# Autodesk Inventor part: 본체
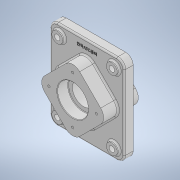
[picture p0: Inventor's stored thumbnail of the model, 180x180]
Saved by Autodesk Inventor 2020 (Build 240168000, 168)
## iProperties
Created: 2021-07
Part Number: 본체
Material: 일반
Document SubType Name: Modeling
Designer: Owner
Density: 1 g/cm^3
Appearance: 기본값
Mass: 807.977 g
Surface Area: 961.758 cm^2
Volume: 807.977 cm^3
Author: Owner
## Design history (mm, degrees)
sketch "스케치1"
  geometry: L1 (75, -90)-(-75, -90); L2 (-75, -90)-(-75, 90); L3 (-75, 90)-(75, 90); L4 (75, 90)-(75, -90); L5 (75, -90)-(-75, 90); L6 (-75, -90)-(75, 90); 1 further point
  constraints: 12 end point, 2 midpoint, 2 parallel, 1 horizontal, 1 perpendicular
  dimensions: "d0" = 150 distance of L2.end L3.end; "d1" = 180 distance of L1.end L2.end
extrude "돌출1" new body sketch "스케치1" stored distance "d2" = 18; taper "d3" = 0 deg
fillet "모깎기1" dims "d4" = 15
sketch "스케치2" dims "d7" = 29
  geometry: L1 (0, -70.711)-(-70.711, 0); L2 (-70.711, 0)-(0, 70.711); L3 (0, 70.711)-(70.711, 0); L4 (70.711, 0)-(0, -70.711); L5 (0, -70.711)-(0, 70.711); L6 (-70.711, 0)-(70.711, 0); 4 further points
  constraints: 12 end point, 4 midpoint, 2 parallel, 1 coincident, 1 horizontal alignment, 1 perpendicular, 1 vertical alignment
  dimensions: "d70" = 100 distance of L1.start L1.end
extrude "돌출2" join sketch "스케치2" distance "d7" = 29; taper "d8" = 0 deg
sketch "스케치3"
  geometry: L1 (-14.142, -56.569)-(-56.569, -14.142); L2 (-56.569, 14.142)-(-14.142, 56.569); L3 (14.142, 56.569)-(56.569, 14.142); L4 (56.569, -14.142)-(14.142, -56.569); L5 (0, -70.711)-(0, 70.711); L6 (-70.711, 0)-(70.711, 0); A1 r 20 centre (-42.426, 0) between (-56.569, 14.142) and (-56.569, -14.142); A2 r 20 centre (0, -42.426) between (-14.142, -56.569) and (14.142, -56.569); A3 r 20 centre (42.426, 0) between (56.569, -14.142) and (56.569, 14.142); A4 r 20 centre (0, 42.426) between (14.142, 56.569) and (-14.142, 56.569); 3 further points
  constraints: 12 end point, 8 point on circle, 8 point on line, 8 tangent, 4 centre point, 4 midpoint, 3 equal radius, 2 parallel, 1 horizontal alignment, 1 perpendicular, 1 vertical alignment
  dimensions: "d9" = 100 distance of L5.start L6.start; "d12" = 20 radius of A1 (derived)
extrude "돌출3" join sketch "스케치3" distance "d10" = 23; taper "d11" = 0 deg
sketch "스케치4"
  geometry: C1 r 11 at (-55, 70); C2 r 11 at (55, 70); C3 r 11 at (55, -70); C4 r 11 at (-55, -70); 1 further point
  constraints: 4 centre point, 2 horizontal alignment, 2 vertical alignment
  dimensions: "d13" = 22 diameter of C1; "d14" = 22 diameter of C2; "d15" = 22 diameter of C3; "d16" = 22 diameter of C4; "d17" = 110 distance of C1.centre C2.centre; "d18" = 55 horizontal distance of point (0, 0) C1.centre (= 0.5 x d17); "d19" = 140 distance of C3.centre C2.centre; "d20" = 70 vertical distance of point (0, 0) C2.centre (= 0.5 x d19)
extrude "돌출4" join sketch "스케치4" distance "d21" = 5; taper "d22" = 0 deg
sketch "스케치5"
  geometry: C1 r 11 at (0, 0) reference; C2 r 11 at (110, 0) reference; C3 r 11 at (110, -140) reference; C4 r 11 at (0, -140) reference; 5 further points
  constraints: 4 coincident
hole "구멍1" sketch "스케치5" at (0, 0), (110, 0), (110, -140), (0, -140) diameter "d23" = 11; stored, may be unused: countersink angle "d27" = 90 deg, drill point angle "d29" = 118 deg; dims "d24" = 6, "d25" = 4, "d26" = 2, "d28" = 8
sketch "스케치6"
  geometry: 2 further points
  constraints: 1 vertical alignment
  dimensions: "d30" = 48 distance of point (0, 0) point (0, 48)
hole "구멍2" sketch "스케치6" at (0, 48) diameter "d31" = 4.917; stored, may be unused: countersink angle "d35" = 90 deg, drill point angle "d37" = 118 deg; dims "d32" = 10, "d33" = 4, "d34" = 2, "d36" = 13
sketch "스케치7"
  geometry: 2 further points
  constraints: 1 coincident
hole "구멍3" sketch "스케치7" at (0, 0) diameter "d41" = 45; stored, may be unused: countersink angle "d45" = 90 deg, drill point angle "d47" = 118 deg; dims "d42" = 10, "d43" = 62, "d44" = 22, "d46" = 13
chamfer "모따기1" distance "d48" = 1; stored, may be unused: second distance "d49" = 2, angle "d50" = 45 deg
fillet "모깎기2" dims "d51" = 1
sketch "스케치8"
  geometry: 2 further points
  constraints: 1 vertical alignment
  dimensions: "d52" = 48 distance of point (0, 0) point (0, 48)
hole "구멍4" sketch "스케치8" at (0, 48) diameter "d53" = 4.917; stored, may be unused: countersink angle "d57" = 90 deg, drill point angle "d59" = 118 deg; dims "d54" = 10, "d55" = 62, "d56" = 22, "d58" = 13
fillet "모깎기3" dims "d63" = 3
sketch "스케치9"
  geometry: L1 (60, 90)-(-60, 90) reference; 2 further points
  constraints: 1 vertical alignment, 1 other
  dimensions: "d64" = 15 distance from line of point (0, 75) L1
feature "엠보싱1" sketch "스케치9" dims "d0" = 150, "d1" = 180, "d10" = 23, "d65" = 0.5, "d66" = 0
fillet "모깎기4" dims "d67" = 3
fillet "모깎기6" dims "d69" = 3
fillet "모깎기7" dims "d71" = 20
fillet "모깎기8" dims "d72" = 3
sketch "스케치10"
  geometry: C1 r 31 at (0, 0); 1 further point
  constraints: 1 centre point, 1 coincident
  dimensions: "d73" = 62 diameter of C1
extrude "돌출5" cut sketch "스케치10" distance "d74" = 22; taper "d75" = 0 deg
fillet "모깎기9" dims "d76" = 1
chamfer "모따기2" distance "d77" = 1; stored, may be unused: second distance "d78" = 2, angle "d79" = 45 deg
node "솔리드1"
pattern_circular "원형 패턴1" dims angle "d39" = 360 deg
pattern_circular "원형 패턴2" dims angle "d61" = 360 deg
feature "A9D066F2-1C7D-4E18-AEED-F7BC21143FA4" dims "d23" = 11, "d24" = 6, "d25" = 4, "d26" = 2, "d27" = 90 deg, "d28" = 8, "d29" = 118 deg
